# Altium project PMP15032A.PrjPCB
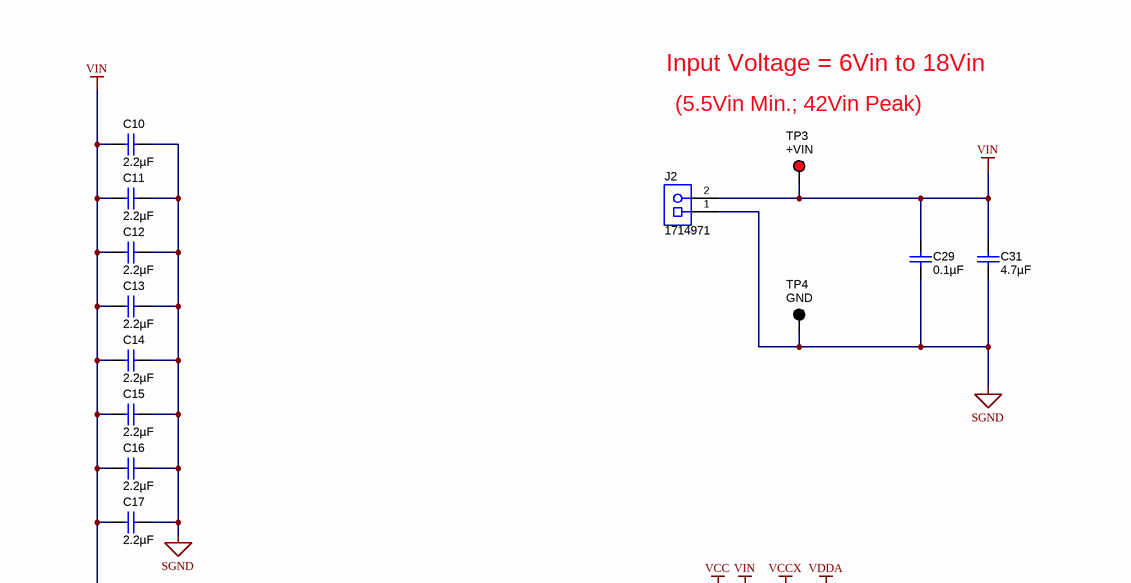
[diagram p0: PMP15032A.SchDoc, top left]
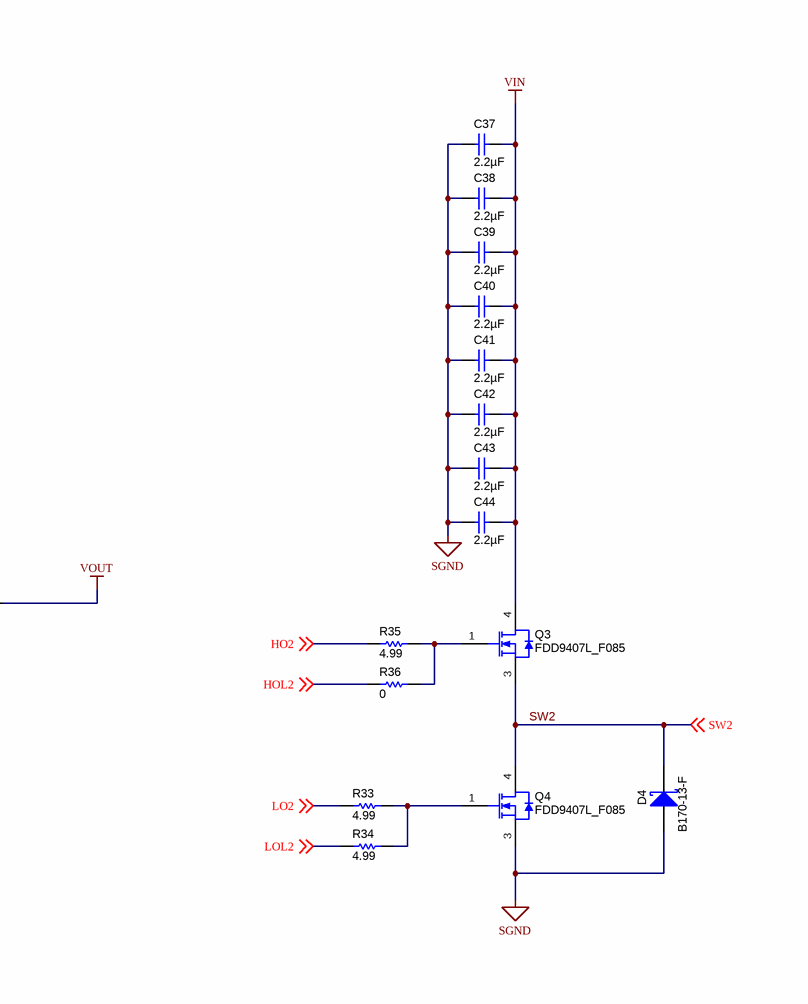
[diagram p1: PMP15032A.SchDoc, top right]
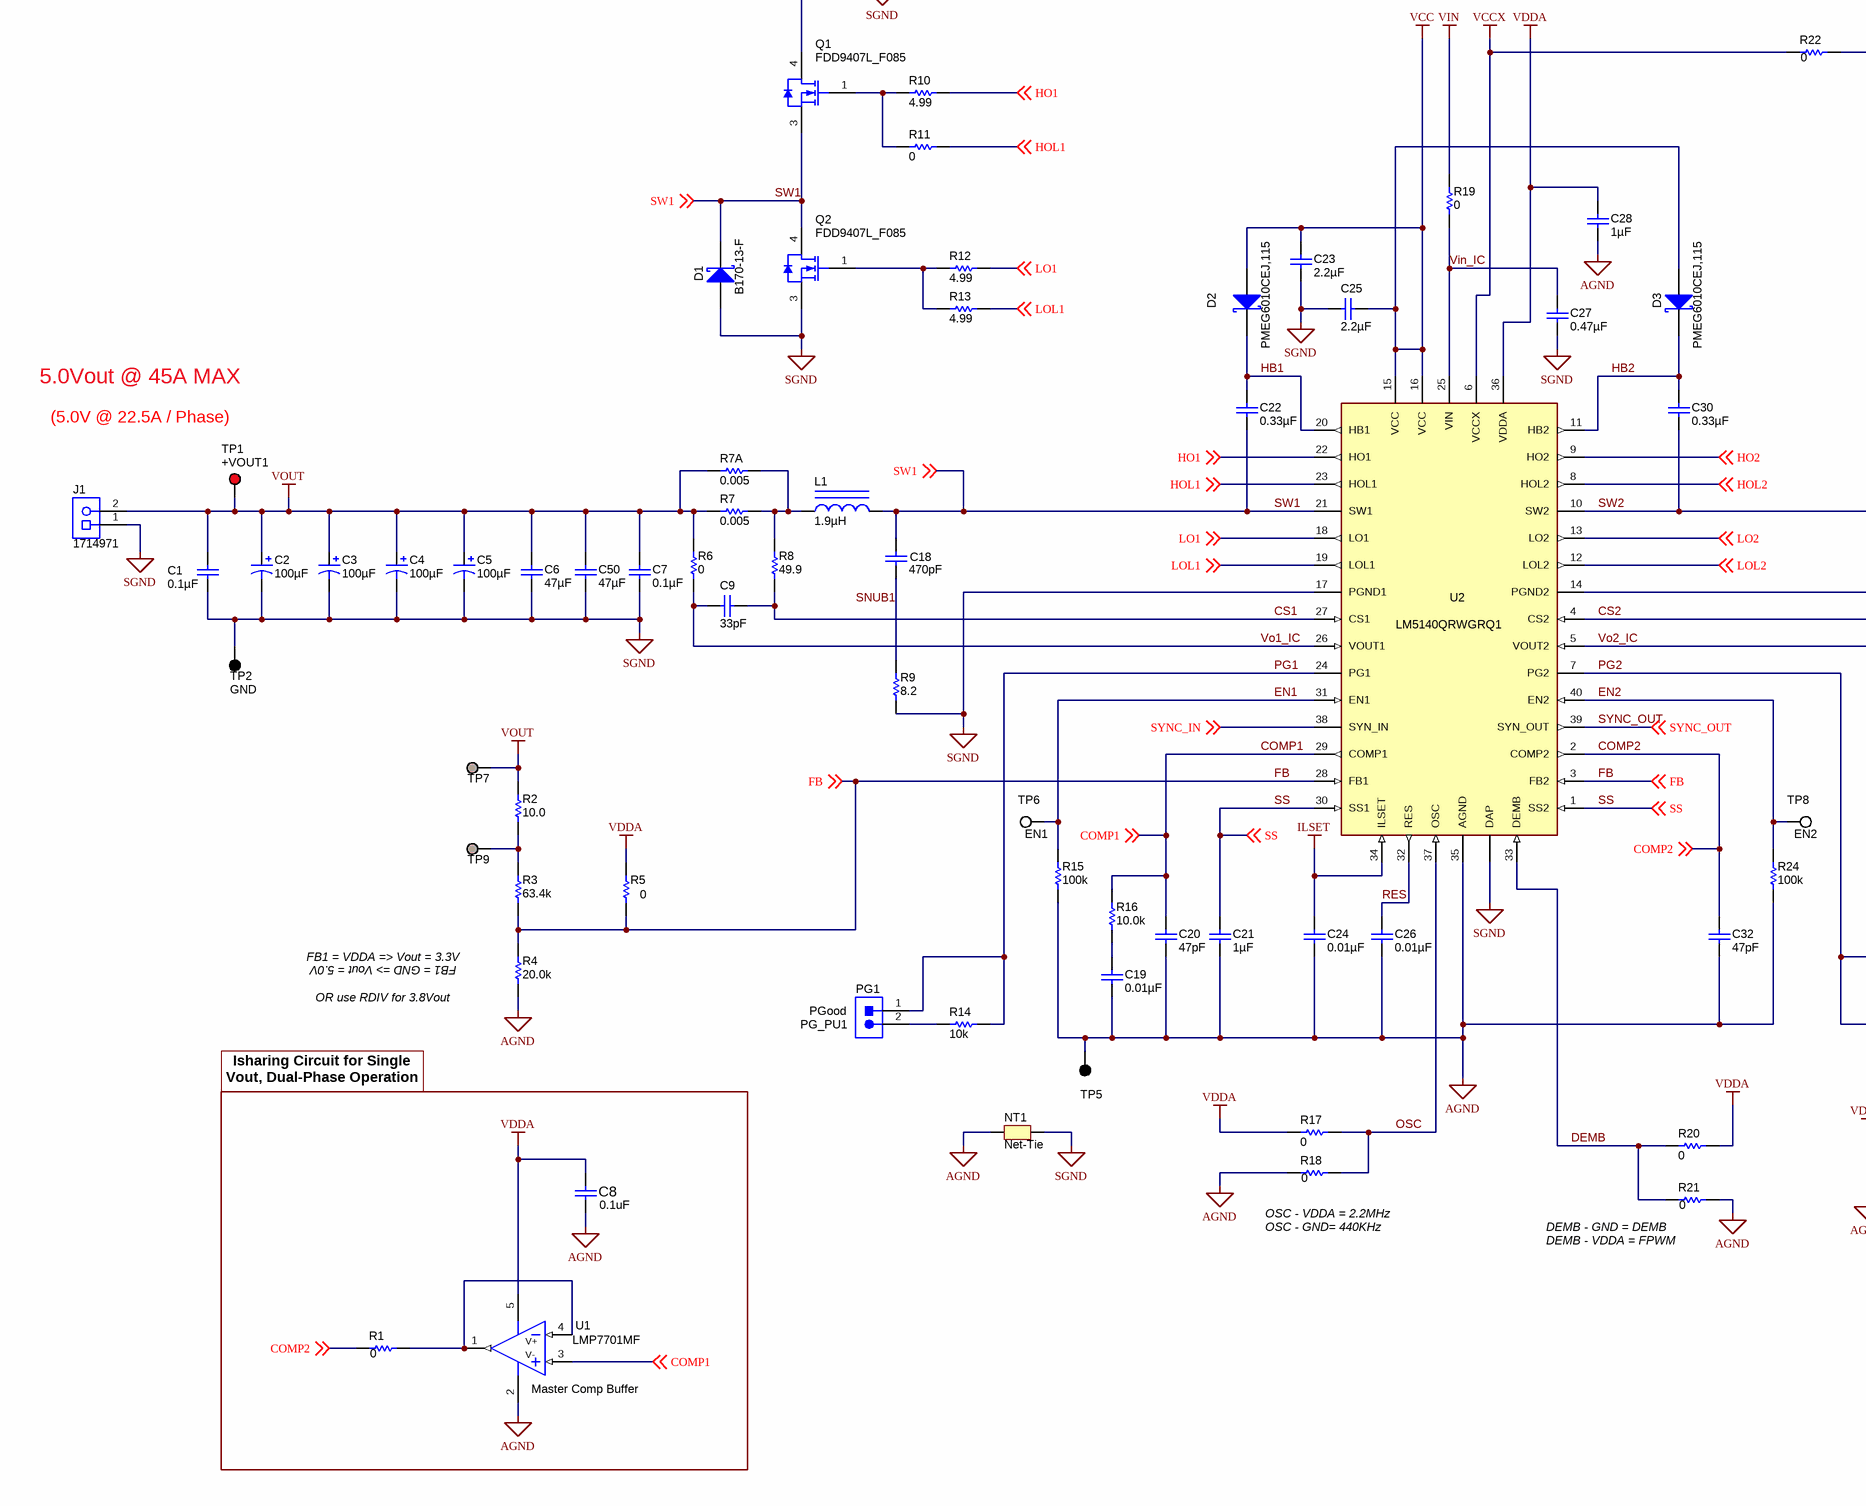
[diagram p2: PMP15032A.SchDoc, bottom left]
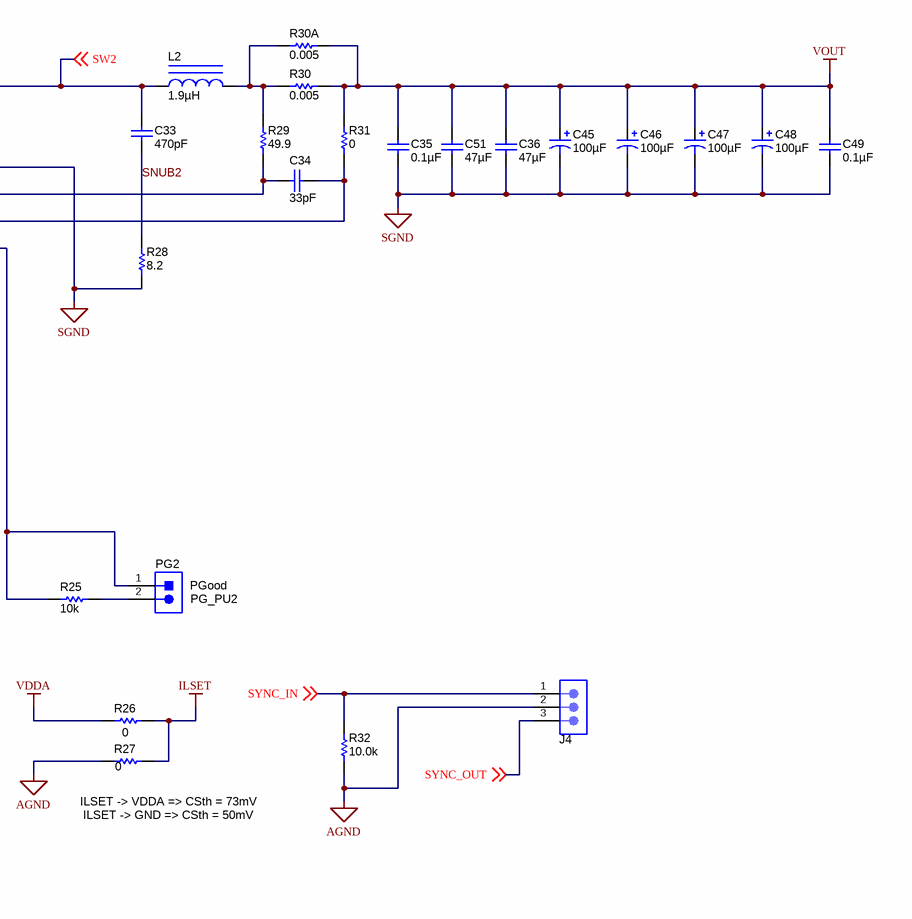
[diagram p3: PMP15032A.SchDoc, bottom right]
TID: PMP15032; TechSupport: http://www.ti.com/support; SCH_Rev: A; PRJ_Title: LM5140 Dual Interleaved Sync Buck (AEQ); PRJ_Number: PMP15032; PRJ_Engineer: T Allinder; PCB_Rev: A; PCB_Layout: K Nielson; EVM_Orderable: N/A; CopyrightYear: 2016
2 sheets, 128 parts. Net scope: global (net labels, ports and power ports of the same name join across sheets).
Board file: PMP15032A.PcbDoc
Sheets:
  PMP15032A.SchDoc
  PMP15032A-HW.SchDoc

## Sheet PMP15032A.SchDoc: Schematic
size 558 x 431 mm; Date: Not shown in title block; ApprovedBy: Not shown in title block; CheckedBy: Not shown in title block; Author: Not shown in title block; CompanyName: Not shown in title block; Engineer: Not shown in title block; Organization: Not shown in title block; Address1: Not shown in title block; Address2: Not shown in title block; Address3: Not shown in title block; Address4: Not shown in title block; DocumentNumber: 1; Revision: Use project parameter SCH_Rev; SheetNumber: 1; SheetTotal: 2; PageSetup: Record=PageOptions¦CenterHorizontal=True¦CenterVertical=True¦PrintScale=0.62¦XCorrection=1.00¦YCorrection=1.00¦PrintKind=0¦BorderSize=5000000¦LeftOffset=0¦BottomOffset=0¦Orientation=2¦PaperLength=1000¦PaperWidth=1000¦Scale=100¦PaperSource=15¦PrintQuality=-3¦MediaType=1¦DitherType=10¦PrintScaleMode=1¦PaperKind=11x17¦PaperIndex=17

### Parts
C1  ValueDisplayed: 0.1µF  [0603L]  (hidden comment: GRM188R72A104KA35D)
C2  100µF  [7343-31]
C3  100µF  [7343-31]
C4  100µF  [7343-31]
C5  100µF  [7343-31]
C6  ValueDisplayed: 47µF  [1206]  (hidden comment: C3216X5R1C476M160AB)
C7  ValueDisplayed: 0.1µF  [0603L]  (hidden comment: GRM188R72A104KA35D)
C8  0.1uF  [0603]
C9  ValueDisplayed: 33pF  [0603L]  (hidden comment: 06031A330JAT2A)
C10  ValueDisplayed: 2.2µF  [1206_190]  (hidden comment: CGA5L3X7S2A225M160AB)
C11  ValueDisplayed: 2.2µF  [1206_190]  (hidden comment: CGA5L3X7S2A225M160AB)
C12  ValueDisplayed: 2.2µF  [1206_190]  (hidden comment: CGA5L3X7S2A225M160AB)
C13  ValueDisplayed: 2.2µF  [1206_190]  (hidden comment: CGA5L3X7S2A225M160AB)
C14  ValueDisplayed: 2.2µF  [1206_190]  (hidden comment: CGA5L3X7S2A225M160AB)
C15  ValueDisplayed: 2.2µF  [1206_190]  (hidden comment: CGA5L3X7S2A225M160AB)
C16  ValueDisplayed: 2.2µF  [1206_190]  (hidden comment: CGA5L3X7S2A225M160AB)
C17  ValueDisplayed: 2.2µF  [1206_190]  (hidden comment: CGA5L3X7S2A225M160AB)
C18  ValueDisplayed: 470pF  [0805_HV]  (hidden comment: 08051A471JAT2A)
C19  ValueDisplayed: 0.01µF  [0603L]  (hidden comment: GRM188R71E103KA01D)
C20  ValueDisplayed: 47pF  [0603L]  (hidden comment: C0603C470J5GACTU)
C21  ValueDisplayed: 1µF  [0603L]  (hidden comment: C1608X7R1E105K080AB)
C22  ValueDisplayed: 0.33µF  [0603L]  (hidden comment: CGA3E3X7R1H334K080AB)
C23  ValueDisplayed: 2.2µF  [0603_HV]  (hidden comment: C0603C225M8PACTU)
C24  ValueDisplayed: 0.01µF  [0603L]  (hidden comment: GRM188R71H103KA01D)
C25  ValueDisplayed: 2.2µF  [0603_HV]  (hidden comment: C0603C225M8PACTU)
C26  ValueDisplayed: 0.01µF  [0603L]  (hidden comment: GRM188R71H103KA01D)
C27  ValueDisplayed: 0.47µF  [0805_HV1]  (hidden comment: GRM21BR72A474KA73L)
C28  ValueDisplayed: 1µF  [0603L]  (hidden comment: C1608X7R1E105K080AB)
C29  ValueDisplayed: 0.1µF  [0603]  (hidden comment: GRM188R72A104KA35J)
C30  ValueDisplayed: 0.33µF  [0603L]  (hidden comment: CGA3E3X7R1H334K080AB)
C31  ValueDisplayed: 4.7µF  [1210_220]  (hidden comment: CGA6M3X7S2A475K200AB)
C32  ValueDisplayed: 47pF  [0603L]  (hidden comment: C0603C470J5GACTU)
C33  ValueDisplayed: 470pF  [0805_HV]  (hidden comment: 08051A471JAT2A)
C34  ValueDisplayed: 33pF  [0603L]  (hidden comment: 06031A330JAT2A)
C35  ValueDisplayed: 0.1µF  [0603L]  (hidden comment: GRM188R72A104KA35D)
C36  ValueDisplayed: 47µF  [1206]  (hidden comment: C3216X5R1C476M160AB)
C37  ValueDisplayed: 2.2µF  [1206_190]  (hidden comment: CGA5L3X7S2A225M160AB)
C38  ValueDisplayed: 2.2µF  [1206_190]  (hidden comment: CGA5L3X7S2A225M160AB)
C39  ValueDisplayed: 2.2µF  [1206_190]  (hidden comment: CGA5L3X7S2A225M160AB)
C40  ValueDisplayed: 2.2µF  [1206_190]  (hidden comment: CGA5L3X7S2A225M160AB)
C41  ValueDisplayed: 2.2µF  [1206_190]  (hidden comment: CGA5L3X7S2A225M160AB)
C42  ValueDisplayed: 2.2µF  [1206_190]  (hidden comment: CGA5L3X7S2A225M160AB)
C43  ValueDisplayed: 2.2µF  [1206_190]  (hidden comment: CGA5L3X7S2A225M160AB)
C44  ValueDisplayed: 2.2µF  [1206_190]  (hidden comment: CGA5L3X7S2A225M160AB)
C45  100µF  [7343-31]
C46  100µF  [7343-31]
C47  100µF  [7343-31]
C48  100µF  [7343-31]
C49  ValueDisplayed: 0.1µF  [0603L]  (hidden comment: GRM188R72A104KA35D)
C50  ValueDisplayed: 47µF  [1206]  (hidden comment: C3216X5R1C476M160AB)
C51  ValueDisplayed: 47µF  [1206]  (hidden comment: C3216X5R1C476M160AB)
D1  B170-13-F  [SMA]
D2  PMEG6010CEJ,115  [SOD-323F]
D3  PMEG6010CEJ,115  [SOD-323F]
D4  B170-13-F  [SMA]
J1  1714971  [Phoenix_1714971]
J2  1714971  [Phoenix_1714971]
J4  PBC03SAAN  [PBC03SAAN]  (value not drawn)
L1  ValueDisplayed: 1.9µH  [WE-HCB_1890]  (hidden comment: 7443556190)
L2  ValueDisplayed: 1.9µH  [WE-HCB_1890]  (hidden comment: 7443556190)
NT1  Net-Tie  [Net-Tie_10mil]  (net tie, no BOM)
PG1  PEC01DAAN  [Sullins_PxC01DAAN]  (value not drawn)
PG2  PEC01DAAN  [Sullins_PxC01DAAN]  (value not drawn)
Q1  FDD9407L_F085  [DDPAK]
Q2  FDD9407L_F085  [DDPAK]
Q3  FDD9407L_F085  [DDPAK]
Q4  FDD9407L_F085  [DDPAK]
R1  0  [0603L]
R2  ValueDisplayed: 10.0  [0603L]  (hidden comment: CRCW060310R0FKEA)
R3  ValueDisplayed: 63.4k  [0603L]  (hidden comment: CRCW060363K4FKEA)
R4  ValueDisplayed: 20.0k  [0603L]  (hidden comment: CRCW060320K0FKEA)
R5  0  [0603L]
R6  ValueDisplayed: 0  [0603L]  (hidden comment: CRCW06030000Z0EA)
R7  ValueDisplayed: 0.005  [KRL2012]  (hidden comment: KRL2012M-R005-F-T1)
R7A  ValueDisplayed: 0.005  [KRL2012]  (hidden comment: KRL2012M-R005-F-T1)
R8  ValueDisplayed: 49.9  [0603L]  (hidden comment: CRCW060349R9FKEA)
R9  ValueDisplayed: 8.2  [2010L]  (hidden comment: CRCW20108R20JNEF)
R10  ValueDisplayed: 4.99  [0603L]  (hidden comment: CRCW06034R99FKEA)
R11  ValueDisplayed: 0  [0603L]  (hidden comment: CRCW06030000Z0EA)
R12  ValueDisplayed: 4.99  [0603L]  (hidden comment: CRCW06034R99FKEA)
R13  ValueDisplayed: 4.99  [0603L]  (hidden comment: CRCW06034R99FKEA)
R14  ValueDisplayed: 10k  [0603L]  (hidden comment: CRCW060310K0JNEA)
R15  100k  [0603L]
R16  ValueDisplayed: 10.0k  [0603L]  (hidden comment: CRCW060310K0FKEA)
R17  value 0  [0603L]  (hidden comment: RC0603JR-070RL)
R18  0  [0603L]
R19  ValueDisplayed: 0  [0603L]  (hidden comment: CRCW06030000Z0EA)
R20  ValueDisplayed: 0  [0603L]  (hidden comment: CRCW06030000Z0EA)
R21  0  [0603L]
R22  0  [0603L]
R24  100k  [0603L]
R25  ValueDisplayed: 10k  [0603L]  (hidden comment: CRCW060310K0JNEA)
R26  0  [0603L]
R27  0  [0603L]
R28  ValueDisplayed: 8.2  [2010L]  (hidden comment: CRCW20108R20JNEF)
R29  ValueDisplayed: 49.9  [0603L]  (hidden comment: CRCW060349R9FKEA)
R30  ValueDisplayed: 0.005  [KRL2012]  (hidden comment: KRL2012M-R005-F-T1)
R30A  ValueDisplayed: 0.005  [KRL2012]  (hidden comment: KRL2012M-R005-F-T1)
R31  ValueDisplayed: 0  [0603L]  (hidden comment: CRCW06030000Z0EA)
R32  ValueDisplayed: 10.0k  [0603L]  (hidden comment: CRCW060310K0FKEA)
R33  ValueDisplayed: 4.99  [0603L]  (hidden comment: CRCW06034R99FKEA)
R34  ValueDisplayed: 4.99  [0603L]  (hidden comment: CRCW06034R99FKEA)
R35  ValueDisplayed: 4.99  [0603L]  (hidden comment: CRCW06034R99FKEA)
R36  ValueDisplayed: 0  [0603L]  (hidden comment: CRCW06030000Z0EA)
TP1  +VOUT1  [Keystone5010]
TP2  GND  [Keystone5011]
TP3  +VIN  [Keystone5010]
TP4  GND  [Keystone5011]
TP5  5001  [Keystone5001]  (value not drawn)
TP6  EN1  [Keystone5002]
TP7  TESTPOINT  [TP_VIA_024RND014]  (value not drawn)  (no BOM)
TP8  EN2  [Keystone5002]
TP9  TESTPOINT  [TP_VIA_024RND014]  (value not drawn)  (no BOM)
U1  LMP7701MF  [DBV0005A_N]
U2  LM5140QRWGRQ1  [RWG0040A]

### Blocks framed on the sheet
Master Comp Buffer: C8 R1 U1

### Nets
AGND: C8.2 C19.1 C20.2 C21.2 C24.2 C26.2 C28.2 C32.1 J4.2 NT1.1 R4.1 R15.1 R18.2 R21.1 R24.1 R27.2 R32.1 TP5.1 U1.2(V-) U2.35(AGND)
ILSET: C24.1 R26.1 R27.1 U2.34(ILSET)
SGND: C1.1 C2.2(-) C3.2(-) C4.2(-) C5.2(-) C6.2 C7.1 C10.1 C11.1 C12.1 C13.1 C14.1 C15.1 C16.1 C17.1 C23.2 C25.1 C27.1 C29.2 C31.2 C35.1 C36.2 C37.2 C38.2 C39.2 C40.2 C41.2 C42.2 C43.2 C44.2 C45.2(-) C46.2(-) C47.2(-) C48.2(-) C49.1 C50.2 C51.2 D1.2(A) D4.2(A) J1.1 J2.1 NT1.2 Q2.3(S) Q4.3(S) R9.1 R28.1 TP2.1 TP4.1 U2.14(PGND2) U2.17(PGND1) U2.41(DAP)
VCC: C23.1 C25.2 D2.2(A) D3.2(A) U2.15(VCC) U2.16(VCC)
VCCX: R22.2 U2.6(VCCX)
VDDA: C8.1 C28.1 R5.2 R17.2 R20.1 R26.2 U1.5(V+) U2.36(VDDA)
VIN: C10.2 C11.2 C12.2 C13.2 C14.2 C15.2 C16.2 C17.2 C29.1 C31.1 C37.1 C38.1 C39.1 C40.1 C41.1 C42.1 C43.1 C44.1 J2.2 Q1.4(D) Q3.4(D) R19.2 TP3.1
VOUT: C1.2 C2.1(+) C3.1(+) C4.1(+) C5.1(+) C6.1 C7.2 C35.2 C36.1 C45.1(+) C46.1(+) C47.1(+) C48.1(+) C49.2 C50.1 C51.1 J1.2 R2.2 R6.2 R7.1 R7A.1 R22.1 R30.2 R30A.2 R31.2 TP1.1 TP7.1
COMP1: C20.1 R16.2 U1.3(IN+) U2.29(COMP1) ; off-sheet COMP1
COMP2: C32.2 R1.1 U2.2(COMP2) ; off-sheet COMP2
CS1: C9.1 R8.1 U2.27(CS1)
CS2: C34.2 R29.1 U2.4(CS2)
DEMB: R20.2 R21.2 U2.33(DEMB)
EN1: R15.2 TP6.1 U2.31(EN1)
EN2: R24.2 TP8.1 U2.40(EN2)
FB: R3.1 R4.2 R5.1 U2.3(FB2) U2.28(FB1) ; off-sheet FB
HB1: C22.2 D2.1(K) U2.20(HB1)
HB2: C30.2 D3.1(K) U2.11(HB2)
HO1: R10.2 U2.22(HO1) ; off-sheet HO1
HO2: R35.1 U2.9(HO2) ; off-sheet HO2
HOL1: R11.2 U2.23(HOL1) ; off-sheet HOL1
HOL2: R36.1 U2.8(HOL2) ; off-sheet HOL2
LO1: R12.2 U2.18(LO1) ; off-sheet LO1
LO2: R33.1 U2.13(LO2) ; off-sheet LO2
LOL1: R13.2 U2.19(LOL1) ; off-sheet LOL1
LOL2: R34.1 U2.12(LOL2) ; off-sheet LOL2
OSC: R17.1 R18.1 U2.37(OSC)
PG1: PG1.1 R14.2 U2.24(PG1)
PG2: PG2.1 R25.1 U2.7(PG2)
RES: C26.1 U2.32(RES)
SNUB2: C33.1 R28.2
SS: C21.1 U2.1(SS2) U2.30(SS1) ; off-sheet SS
SW1: C18.1 C22.1 D1.1(K) L1.1 Q1.3(S) Q2.4(D) U2.21(SW1) ; off-sheet SW1
SW2: C30.1 C33.2 D4.1(K) L2.2 Q3.3(S) Q4.4(D) U2.10(SW2) ; off-sheet SW2
SYNC_IN: J4.1 R32.2 U2.38(SYN_IN) ; off-sheet SYNC_IN
SYNC_OUT: J4.3 U2.39(SYN_OUT) ; off-sheet SYNC_OUT
Vin_IC: C27.2 R19.1 U2.25(VIN)
Vo1_IC: C9.2 R6.1 U2.26(VOUT1)
Vo2_IC: C34.1 R31.1 U2.5(VOUT2)
NetC18_2: C18.2 R9.2
NetC19_2: C19.2 R16.1
NetL1_2: L1.2 R7.2 R7A.2 R8.2
NetL2_1: L2.1 R29.2 R30.1 R30A.1
NetPG1_2: PG1.2 R14.1
NetPG2_2: PG2.2 R25.2
NetQ1_1: Q1.1(G) R10.1 R11.1
NetQ2_1: Q2.1(G) R12.1 R13.1
NetQ3_1: Q3.1(G) R35.2 R36.2
NetQ4_1: Q4.1(G) R33.2 R34.2
NetR1_2: R1.2 U1.1(OUT) U1.4(IN-)
NetR2_1: R2.1 R3.2 TP9.1

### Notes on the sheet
- Input Voltage = 6Vin to 18Vin
- (5.5Vin Min.; 42Vin Peak)
- 5.0Vout @ 45A MAX
- (5.0V @ 22.5A / Phase)
- FB1 = VDDA => Vout = 3.3V
- FB1 = GND => Vout = 5.0V
- OR use RDIV for 3.8Vout
- (near PG1) PG_PU1
- (near PG1) PGood
- (near PG2) PGood
- (near PG2) PG_PU2
- Isharing Circuit for Single Vout, Dual-Phase Operation
- (near R18) OSC - GND= 440KHz
- (near R18) OSC - VDDA = 2.2MHz
- (near R21) DEMB - GND = DEMB
- (near R27) ILSET -> VDDA => CSth = 73mV
- (near R21) DEMB - VDDA = FPWM
- (near R27) ILSET -> GND => CSth = 50mV
- Labels drawn without touching a wire or pin: SNUB1

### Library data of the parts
C1 C7 C35 C49 = GRM188R72A104KA35D: CAP, CERM, 0.1uF, 100V, +/-10%, X7R, 0603; Manufacturer: MuRata; Polarized: N; CompType: Capacitor; U/M: EA; Cap_F: 0.0000001; Tolerance_%: 10; Value1: Unknown; VDC_V: 100; TaMin_C: -55; TaMax_C: 125; Cap_Case: 0603
C2-C5 C45-C48 = T598D107M010ATE025: CAP TANT POLY 100UF 10V 2917; Manufacturer: Kemet; Manufacturer Size Code: D; CompType: Used in some BOM reports.  Useful for finding later.; SymbolVersion: use current date i.e. 2008-05-20; U/M: EA, IN, or GM; Tolerance_%: ±20%; ESR_Ohm: 25 mOhm; SymbolCreator: Use a-id; Lifetime @ Temp.: 1000 Hrs @ 125°C; Type: Molded
C6 C36 C50 C51 = C3216X5R1C476M160AB: CAP, CERM, 47uF, 16V, +/-15%, X5R, 1206; Manufacturer: TDK; Polarized: N; CompType: Capacitor; U/M: EA; Cap_F: 0.000047; Tolerance_%: 15; Value1: Unknown; VDC_V: 16; TaMin_C: -55; TaMax_C: 85
C8 = C0603C104K4RACTU: CAP, CERM, 0.1uF, 16V, +/-10%, X7R, 0603; Manufacturer: Kemet; Polarized: N; TaMax_C: 125; TaMin_C: -55; Tolerance_%: 10; VDC_V: 16; Cap_F: 0.0000001; CompType: Capacitor; ValueDisplayed: 0.1µF; U/M: EA
C9 C34 = 06031A330JAT2A: CAP, CERM, 33 pF, 100 V, +/- 5%, C0G/NP0, 0603; Manufacturer: AVX; Polarized: N; CompType: Capacitor; Value: 33pF; U/M: EA; Cap_F: 0.000000000033; Tolerance_%: 5; ESR_ohm: 0.209; Value1: 0.209 ohm; VDC_V: 100; Value2: 100V; TaMin_C: -55; TaMax_C: 125; Cap_Case: 0603
C10-C17 C37-C44 = CGA5L3X7S2A225M160AB: CAP, CERM, 2.2 µF, 100 V, +/- 20%, X7S, AEC-Q200 Grade 1, 1206_190; Manufacturer: TDK; CompType: Capacitor; U/M: EA; Value: 2.2uF; Tolerance_%: 20; VDC_V: 100; Polarized: N; Cap_F: 0.0000022; Value1: Unknown; Value2: 100V; TaMin_C: -55; TaMax_C: 125; Cap_Case: 1206; SizeArea_mm2: 5.12; SizeAreaWB_mm2: 10.92; SizeX_mm: 3.2; SizeY_mm: 1.6; SizeZ_mm: 1.9; AEC Category: Q200; AEC Qualified: Y; AEC Grade: 1
C18 C33 = 08051A471JAT2A: CAP, CERM, 470 pF, 100 V, +/- 5%, C0G/NP0, 0805; Manufacturer: AVX; Polarized: N; CompType: Capacitor; Value: 470pF; U/M: EA; Cap_F: 0.00000000047; Tolerance_%: 5; ESR_ohm: 0.159; Value1: 0.159 ohm; VDC_V: 100; Value2: 100V; TaMin_C: -55; TaMax_C: 125; Cap_Case: 0805
C19 = GRM188R71E103KA01D: CAP, CERM, 0.01 µF, 25 V, +/- 10%, X7R, 0603; Manufacturer: MuRata; Polarized: N; CompType: Capacitor; Value: 0.01uF; U/M: EA; Cap_F: 0.00000001; Tolerance_%: 10; Value1: Unknown; VDC_V: 25; Value2: 25V; TaMin_C: -55; TaMax_C: 125; Cap_Case: 0603; AEC Category: Q200
C20 C32 = C0603C470J5GACTU: CAP, CERM, 47 pF, 50 V, +/- 5%, C0G/NP0, 0603; Manufacturer: Kemet; Polarized: N; CompType: Capacitor; Value: 47pF; U/M: EA; Cap_F: 0.000000000047; Tolerance_%: 5; Value1: Unknown; VDC_V: 50; Value2: 50V; TaMin_C: -55; TaMax_C: 125; Cap_Case: 0603; AEC Category: Q200
C21 C28 = C1608X7R1E105K080AB: CAP, CERM, 1 µF, 25 V, +/- 10%, X7R, 0603; Manufacturer: TDK; Polarized: N; CompType: Capacitor; Value: 1uF; U/M: EA; Cap_F: 0.000001; Tolerance_%: 10; Value1: Unknown; VDC_V: 25; Value2: 25V; TaMin_C: -55; TaMax_C: 125; Cap_Case: 0603; AEC Category: Q200
C22 C30 = CGA3E3X7R1H334K080AB: CAP, CERM, 0.33 µF, 50 V, +/- 10%, X7R, AEC-Q200 Grade 1, 0603; Manufacturer: TDK; Polarized: N; CompType: Capacitor; Value: 0.33uF; U/M: EA; Cap_F: 0.00000033; Tolerance_%: 10; ESR_ohm: 0.01584; Value1: 0.01584 ohm; VDC_V: 50; Value2: 50V; IRMS_A: 1.31353; TaMin_C: -55; TaMax_C: 125; Cap_Case: 0603; SizeArea_mm2: 1.28; SizeAreaWB_mm2: 4.68; SizeX_mm: 1.6; SizeY_mm: 0.8; SizeZ_mm: 1; AEC Category: Q200; AEC Qualified: Y
C23 C25 = C0603C225M8PACTU: CAP, CERM, 2.2 µF, 10 V, +/- 20%, X5R, 0603; Manufacturer: Kemet; Polarized: N; CompType: Capacitor; Value: 2.2uF; U/M: EA; Cap_F: 0.0000022; Tolerance_%: 20; Value1: Unknown; VDC_V: 10; Value2: 10V; TaMin_C: -55; TaMax_C: 85; Cap_Case: 0603
C24 C26 = GRM188R71H103KA01D: CAP, CERM, 0.01uF, 50V, +/-10%, X7R, 0603; Manufacturer: MuRata; Polarized: N; CompType: Capacitor; U/M: EA; Cap_F: 0.00000001; Tolerance_%: 10; Value1: Unknown; VDC_V: 50; TaMin_C: -55; TaMax_C: 125; Cap_Case: 0603
C27 = GRM21BR72A474KA73L: CAP, CERM, 0.47uF, 100V, +/-10%, X7R, 0805; Manufacturer: MuRata; Polarized: N; CompType: Capacitor; U/M: EA; Cap_F: 0.00000047; Tolerance_%: 10; Value1: Unknown; VDC_V: 100; TaMin_C: -55; TaMax_C: 125; Cap_Case: 0805
C29 = GRM188R72A104KA35J: CAP, CERM, 0.1 µF, 100 V, +/- 10%, X7R, 0603; Manufacturer: MuRata; Polarized: N; CompType: Capacitor; Value: 0.1uF; U/M: EA; Cap_F: 0.0000001; Tolerance_%: 10; Value1: Unknown; VDC_V: 100; Value2: 100V; TaMin_C: -55; TaMax_C: 125; SizeArea_mm2: 1.28; SizeAreaWB_mm2: 4.68; SizeX_mm: 1.6; SizeY_mm: 0.8; SizeZ_mm: 1; AEC Category: Q200
C31 = CGA6M3X7S2A475K200AB: CAP, CERM, 4.7 µF, 100 V, +/- 10%, X7S, AEC-Q200 Grade 1, 1210; Manufacturer: TDK; Polarized: N; CompType: Capacitor; Value: 4.7uF; U/M: EA; Cap_F: 0.0000047; Tolerance_%: 10; ESR_ohm: 0.004236; Value1: 0.004236 ohm; VDC_V: 100; Value2: 100V; IRMS_A: 3.57337; TaMin_C: -55; TaMax_C: 125; SizeArea_mm2: 8; SizeAreaWB_mm2: 14.7; SizeX_mm: 3.2; SizeY_mm: 2.5; SizeZ_mm: 2.2; AEC Category: Q200; AEC Qualified: Y; AEC Grade: 1
D1 D4 = B170-13-F: Diode, Schottky, 70V, 1A, SMA; Manufacturer: Diodes Inc.; U/M: EA; Vr_V: 70; Io_A: 1; Vf_V: 0.79; Value2: 0.79V; TJmax_C: 150; RJC_CperW: 25
D2 D3 = PMEG6010CEJ,115: Diode, Schottky, 60 V, 1 A, SOD-323F; Manufacturer: NXP Semiconductor; U/M: EA; Vf_V: 0.66; Value: 60V; Value1: 1A; Value2: 0.66V; Io_A: 1; Vr_V: 60; TJmax_C: 150
J1 J2 = 1714971: Receptacle, 9.52mm, 2x1, TH; Manufacturer: Phoenix Contact; SymbolCreator: a0412235; Pitch_mm: 9.52; Gender: Female; Row_Count: 1; Current_A: 32; Voltage_V: 1000; Cert_CSA: Y
J4 = PBC03SAAN: Header, 100mil, 3x1, Gold, TH; Manufacturer: Sullins Connector Solutions
L1 L2 = 7443556190: Inductor, Shielded Drum Core, WE-Superflux200, 1.9 µH, 32.5 A, 0.0012 ohm, SMD; Manufacturer: Wurth Elektronik; Value: 1.9uH; Ind_H: 1.9E-6; Imax_A: 32.5; Irms: 32.5A @ 50C rise; Isat: 52A @ 30% inductance drop; DCR_ohm: 0.0012; Value2: 32.5A; SizeAreaWB_mm2: 410.06; SizeArea_mm2: 333.06; SizeX_mm: 18.3; SizeY_mm: 18.2; SizeZ_mm: 9.2; AEC Category: Q200
NT1 = Net-Tie: Single point connection between nets.; SymbolCreator: codlsc
PG1 PG2 = PEC01DAAN: Header, 2.54mm, 1x2, Tin, Black, TH; Manufacturer: Sullins Connector Solutions; SymbolCreator: a0412235; Pitch_mm: 2.54; Gender: Male; Shrouded: N; Row_Count: 2; Current_A: 3; Voltage_V: 1800; Cert_UL: Y
Q1 Q2 = FDD9407L_F085: MOSFET N-CH 40V 100A; Manufacturer: ON Semiconductor/Fairchild; SymbolVersion: use current date i.e. 2008-05-20; SymbolCreator: Use a-id; CompType: Used in some BOM reports.  Useful for finding later.; U/M: EA, IN, or GM; Rds On (Max) @ Id, Vgs: 2.4 mOhm @ 80A, 4.5V; FET Type: MOSFET N-Channel, Metal Oxide; Input Capacitance (Ciss) @ Vds: 6700pF @ 25V; Power - Max: 227W; Gate Charge (Qg) @ Vgs: 125nC @ 10V; Vgs(th) (Max) @ Id: 3V @ 250µA; FET Feature: Logic Level Gate; Current - Continuous Drain (Id) @ 25°C: 100A (Tc)
Q3 Q4 = FDD9407L_F085: MOSFET N-CH 40V 100A; Manufacturer: ON Semiconductor/Fairchild; SymbolVersion: use current date i.e. 2008-05-20; CompType: Used in some BOM reports.  Useful for finding later.; U/M: EA, IN, or GM; SymbolCreator: Use a-id; Rds On (Max) @ Id, Vgs: 2.4 mOhm @ 80A, 4.5V; FET Type: MOSFET N-Channel, Metal Oxide; Input Capacitance (Ciss) @ Vds: 6700pF @ 25V; Power - Max: 227W; Gate Charge (Qg) @ Vgs: 125nC @ 10V; Vgs(th) (Max) @ Id: 3V @ 250µA; FET Feature: Logic Level Gate; Current - Continuous Drain (Id) @ 25°C: 100A (Tc)
R1 = CRCW06030000Z0EA: RES, 0 ohm, 5%, 0.1W, 0603; Manufacturer: Vishay-Dale; CompType: Resistor; Value_Code: 0000; Tolerance_%: 5; Power_W: 0.1; VDC_V: 75; TempCo: 200 ppm/C; EIA_Code: E24; U/M: EA
R2 = CRCW060310R0FKEA: RES, 10.0, 1%, 0.1 W, 0603; Manufacturer: Vishay-Dale; CompType: Resistor; Value: 10.0; Res_ohm: 10; Value_Code: 10R0; Tolerance_%: 1; Power_W: 0.1; Value2: 0.1W; VDC_V: 75; TempCo: 100 ppm/C; EIA_Code: E96; U/M: EA; SizeArea_mm2: 1.28; SizeX_mm: 1.6; SizeY_mm: 0.8; AEC Category: Q200
R3 = CRCW060363K4FKEA: RES, 63.4 k, 1%, 0.1 W, 0603; Manufacturer: Vishay-Dale; CompType: Resistor; Value: 63.4k; Res_ohm: 63400; Value_Code: 63k4; Tolerance_%: 1; Power_W: 0.1; Value2: 0.1W; VDC_V: 75; TempCo: 100 ppm/C; EIA_Code: E96; U/M: EA; SizeArea_mm2: 1.28; SizeX_mm: 1.6; SizeY_mm: 0.8; AEC Category: Q200
R4 = CRCW060320K0FKEA: RES, 20.0 k, 1%, 0.1 W, 0603; Manufacturer: Vishay-Dale; CompType: Resistor; Value: 20.0k; Res_ohm: 20000; Value_Code: 20k0; Tolerance_%: 1; Power_W: 0.1; Value2: 0.1W; VDC_V: 75; TempCo: 100 ppm/C; EIA_Code: E96; U/M: EA; SizeArea_mm2: 1.28; SizeX_mm: 1.6; SizeY_mm: 0.8; AEC Category: Q200
R5 R18 R21 R22 R26 R27 = CRCW06030000Z0EA: RES, 0, 5%, 0.1 W, 0603; Manufacturer: Vishay-Dale; CompType: Resistor; Value_Code: 0000; Tolerance_%: 5; Power_W: 0.1; Value2: 0.1W; VDC_V: 75; TempCo: 200 ppm/C; EIA_Code: E24; U/M: EA
R6 R11 R20 R31 R36 = CRCW06030000Z0EA: RES, 0, 5%, 0.1 W, 0603; Manufacturer: Vishay-Dale; CompType: Resistor; Value: 0; Value_Code: 0000; Tolerance_%: 5; Power_W: 0.1; Value2: 0.1W; VDC_V: 75; TempCo: 200 ppm/C; EIA_Code: E24; U/M: EA
R7 R7A R30 R30A = KRL2012M-R005-F-T1: RES, 0.005, 1%, 1 W, AEC-Q200 Grade 0, 0508; Manufacturer: Susumu Co Ltd; CompType: Resistor; Value: 0.005; Value_Code: 5L000; Tolerance_%: 1; Value2: 1W; TempCo: 25 ppm/C; EIA_Code: E96; U/M: EA; AEC Category: Q200; AEC Qualified: Y; AEC Grade: 0
R8 R29 = CRCW060349R9FKEA: RES, 49.9, 1%, 0.1 W, 0603; Manufacturer: Vishay-Dale; CompType: Resistor; Value: 49.9; Value_Code: 49R9; Tolerance_%: 1; Power_W: 0.1; Value2: 0.1W; VDC_V: 75; TempCo: 100 ppm/C; EIA_Code: E96; U/M: EA
R9 R28 = CRCW20108R20JNEF: RES, 8.2, 5%, 0.75 W, 2010; Manufacturer: Vishay-Dale; CompType: Resistor; Value: 8.2; Value_Code: 8R20; Tolerance_%: 5; Power_W: 0.75; Value2: 0.75W; VDC_V: 400; TempCo: 200 ppm/C; EIA_Code: E24; U/M: EA; AEC Category: Q200
R10 R12 R13 R33-R35 = CRCW06034R99FKEA: RES, 4.99, 1%, 0.1 W, 0603; Manufacturer: Vishay-Dale; CompType: Resistor; Value: 4.99; Value_Code: 4R99; Tolerance_%: 1; Power_W: 0.1; Value2: 0.1W; VDC_V: 75; TempCo: 100 ppm/C; EIA_Code: E96; U/M: EA
R14 R25 = CRCW060310K0JNEA: RES, 10 k, 5%, 0.1 W, 0603; Manufacturer: Vishay-Dale; CompType: Resistor; Value: 10k; Res_ohm: 10000; Value_Code: 10k0; Tolerance_%: 5; Power_W: 0.1; Value2: 0.1W; VDC_V: 75; TempCo: 200 ppm/C; EIA_Code: E24; U/M: EA
R15 R24 = CRCW0603100KJNEA: RES, 100 k, 5%, 0.1 W, 0603; Manufacturer: Vishay-Dale; CompType: Resistor; U/M: EA; Tolerance_%: 5; VDC_V: 75; Value2: 0.1W; TempCo: 200 ppm/C; Res_ohm: 100000; Power_W: 0.1; EIA_Code: E24
R16 = CRCW060310K0FKEA: RES, 10.0 k, 1%, 0.1 W, 0603; Manufacturer: Vishay-Dale; CompType: Resistor; Value: 10.0k; Res_ohm: 10000; Value_Code: 10k0; Tolerance_%: 1; Power_W: 0.1; Value2: 0.1W; VDC_V: 75; TempCo: 100 ppm/C; EIA_Code: E96; U/M: EA; AEC Category: Q200
R17 = RC0603JR-070RL: RES, 0 ohm, 5%, 0.1W, 0603; Manufacturer: Yageo America; CompType: Resistor; Value_Code: 0000; Tolerance_%: 5; Power_W: 0.1; VDC_V: 50; TempCo: 200 ppm/C; EIA_Code: E24; U/M: EA
R19 = CRCW06030000Z0EA: RES, 0, 5%, 0.1 W, 0603; Manufacturer: Vishay-Dale; CompType: Resistor; Value: 0; Value_Code: 0000; Tolerance_%: 5; Power_W: 0.1; Value2: 0.1W; VDC_V: 75; TempCo: 200 ppm/C; EIA_Code: E24; U/M: EA; SizeArea_mm2: 1.28; SizeX_mm: 1.6; SizeY_mm: 0.8; SizeZ_mm: 1; AEC Category: Q200
R32 = CRCW060310K0FKEA: RES, 10.0 k, 1%, 0.1 W, 0603; Manufacturer: Vishay-Dale; CompType: Resistor; Value: 10.0k; Res_ohm: 10000; Value_Code: 10k0; Tolerance_%: 1; Power_W: 0.1; Value2: 0.1W; VDC_V: 75; TempCo: 100 ppm/C; EIA_Code: E96; U/M: EA
TP1 TP3 = 5010: Test Point, Multipurpose, Red, TH; Manufacturer: Keystone; CompType: Test Point Loop; U/M: EA
TP2 TP4 = 5011: Test Point, Multipurpose, Black, TH; Manufacturer: Keystone; CompType: Test Point Loop; U/M: EA
TP5 = 5001: Test Point, Miniature, Black, TH; Manufacturer: Keystone; CompType: Test Point Loop; ContactFinish: Silver
TP6 TP8 = 5002: Test Point, Miniature, White, TH; Manufacturer: Keystone; CompType: Test Point Loop; ContactFinish: Silver
TP7 TP9 = TESTPOINT: TEST POINT.  No entry in BOM.
U1 = LMP7701MF: Precision, Single CMOS Input R-R I/O, 12V Op Amp, DBV0005A; Manufacturer: Texas Instruments; CompType: OpAmp IC
U2 = LM5140RHA: Wide Input Range Dual Synchronous Buck Controller, RHA0040C; Manufacturer: Texas Instruments; SymbolCreator: a0411947; CompType: IC; U/M: EA

## Sheet PMP15032A-HW.SchDoc: Hardware
size 431 x 279 mm; Date: Not shown in title block; ApprovedBy: Not shown in title block; CheckedBy: Not shown in title block; Author: Not shown in title block; CompanyName: Not shown in title block; Engineer: Not shown in title block; Organization: Not shown in title block; Address1: Not shown in title block; Address2: Not shown in title block; Address3: Not shown in title block; Address4: Not shown in title block; DocumentNumber: 2; Revision: Use project parameter SCH_Rev; SheetNumber: 2; SheetTotal: 2; PageSetup: Record=PageOptions¦CenterHorizontal=True¦CenterVertical=True¦PrintScale=1.00¦XCorrection=1.00¦YCorrection=1.00¦PrintKind=0¦BorderSize=5000000¦LeftOffset=0¦BottomOffset=0¦Orientation=2¦PaperLength=1000¦PaperWidth=1000¦Scale=100¦PaperSource=15¦PrintQuality=600¦MediaType=1¦DitherType=10¦PaperKind=Letter¦PrintScaleMode=1
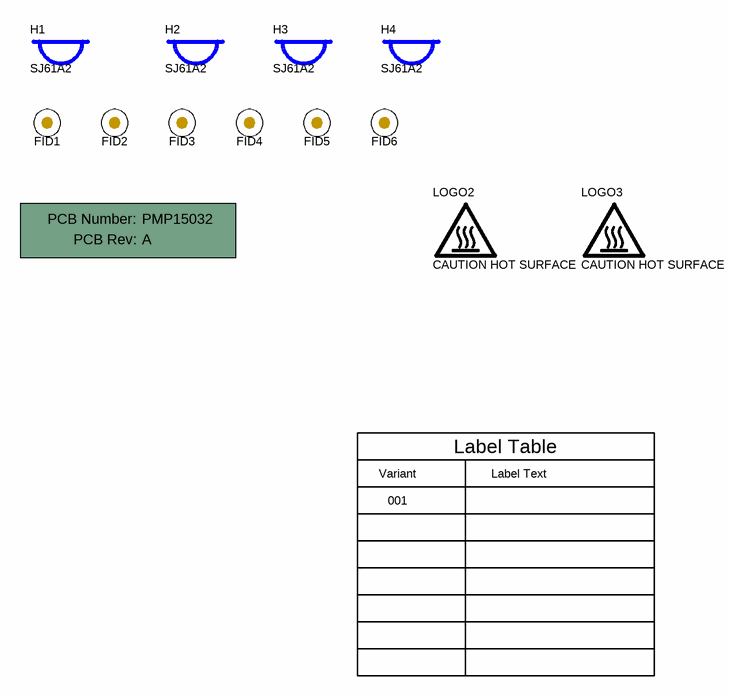
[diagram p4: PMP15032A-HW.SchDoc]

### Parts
!PCB1  Printed Circuit Board  (value not drawn)  (mechanical)
FID1  Fiducial  [Fiducial10-20]  (value not drawn)
FID2  Fiducial  [Fiducial10-20]  (value not drawn)
FID3  Fiducial  [Fiducial10-20]  (value not drawn)
FID4  Fiducial  [Fiducial10-20]  (value not drawn)
FID5  Fiducial  [Fiducial10-20]  (value not drawn)
FID6  Fiducial  [Fiducial10-20]  (value not drawn)
H1  SJ61A2  [Bumpon_SJ61A2]
H2  SJ61A2  [Bumpon_SJ61A2]
H3  SJ61A2  [Bumpon_SJ61A2]
H4  SJ61A2  [Bumpon_SJ61A2]
LOGO2  CAUTION HOT SURFACE  [IEC_HotSurface_Small]  (no BOM)
LOGO3  CAUTION HOT SURFACE  [IEC_HotSurface_Small]  (no BOM)

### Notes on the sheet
- Variant
- Label Table
- Label Text
- 001

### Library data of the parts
!PCB1 = PCB: Manufacturer: Any; PartNumber: PMP15032; SymbolCreator: a0412235
FID1-FID6 = Fiducial: Fiducial mark.  There is nothing to buy or mount.; SymbolCreator: codlsc
H1-H4 = SJ61A2: Bumpon, Hemisphere, 0.375 X 0.235, Black; Manufacturer: 3M; SymbolCreator: a0412235
LOGO2 LOGO3 = IEC_HotSurface: IEC 61010-1 Hot Surface Warning; SymbolCreator: a0412235

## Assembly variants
001: not fitted FID1 FID2 FID3 FID4 FID5 FID6 R5 R18 R21 R27 R32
